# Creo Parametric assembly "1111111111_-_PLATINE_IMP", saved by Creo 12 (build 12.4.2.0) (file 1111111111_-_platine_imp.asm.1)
Units: Custom; MM, KILOGRAM, SECS

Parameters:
  PTC_WM_ITERATION = "0"
  PTC_WM_VERSION = "-.0"
  PTC_WM_LIFECYCLE_STATE = "In Work"
  PTC_WM_LIFECYCLE = "MO_CADDocument"
  PTC_WM_CREATED_BY = "Maximilian Roepper (Z0017RMS: MO)"
  PTC_WM_CREATED_ON = "18-Sep-26 11:36:42 AM"
  PTC_WM_MODIFIED_BY = "Maximilian Roepper (Z0017RMS: MO)"
  PTC_WM_MODIFIED_ON = "18-Sep-26 11:36:46 AM"
  PDMLINKNUMBER = "PDM000071454882"
  PTC_WM_NUMBER = "PDM000071454882"

Other parameters: WEIGHT, WEIGHT_FACTOR, WEIGHT_ADD, MC_ERRORS, SUPPLIER

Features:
  1. coordinate system
  2. imported feature
  3. component "JST_EH_B2B-EH-A_1X02_P2_50MM__1"
  4. component "HX711-2592_1"
  5. component "ESP32_30PIN_1_2"
  6. component "HX711-2592_1"
  7. component "JST_EH_B2B-EH-A_1X02_P2_50MM__1"
  8. component "LCD_MSP2807_FUSION_1"
  9. component "MAR619E_PCB"

Other named items: 1111111111_-_PLATINE_IMP, ROUGH-GROB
